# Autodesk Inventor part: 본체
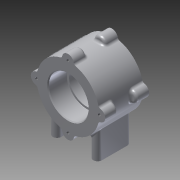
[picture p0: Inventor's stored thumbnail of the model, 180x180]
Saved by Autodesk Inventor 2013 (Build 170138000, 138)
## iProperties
Created: 2015-03
Part Number: 본체
Material: 알루미늄 6061
Document SubType Name: Modeling
Designer: Administrator
Density: 2.71 g/cm^3
Mass: 450.778 g
Surface Area: 332.744 cm^2
Volume: 166.339 cm^3
Author: Administrator
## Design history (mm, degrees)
sketch "스케치1"
  geometry: C1 r 37 at (0, 0); 1 further point
  constraints: 1 centre point, 1 coincident
  dimensions: "d0" = 74 diameter of C1
extrude "돌출1" new body sketch "스케치1" stored distance "d1" = 52; taper "d2" = 0 deg
node "작업 평면1"
sketch "스케치2"
  geometry: L1 (-29, 15)-(-29, -15); L2 (-19, 15)-(-19, -15); L3 (19, 15)-(19, -15); L4 (29, 15)-(29, -15); A1 r 5 centre (-24, 15) between (-19, 15) and (-29, 15); A2 r 5 centre (24, 15) between (29, 15) and (19, 15); A3 r 5 centre (24, -15) between (19, -15) and (29, -15); A4 r 5 centre (-24, -15) between (-29, -15) and (-19, -15); 1 further point
  constraints: 8 end point, 8 point on circle, 7 tangent, 4 centre point, 1 parallel
  dimensions: "d7" = 10 diameter of A1; "d8" = 10 diameter of A2; "d9" = 10 diameter of A3; "d10" = 10 diameter of A4; "d11" = 48 distance of A3.centre A4.centre; "d12" = 15 vertical distance of A2.centre point (0, 0); "d13" = 24 horizontal distance of A2.centre point (0, 0); "d14" = 24 horizontal distance of A1.centre point (0, 0); "d15" = 15 vertical distance of A1.centre point (0, 0); "d16" = 15 vertical distance of A4.centre point (0, 0); "d17" = 24 horizontal distance of point (0, 0) A4.centre; "d18" = 24 horizontal distance of A3.centre point (0, 0)
extrude "돌출2" join sketch "스케치2" stored distance "d19" = 52; taper "d20" = 0 deg
sketch "스케치3"
  geometry: C1 r 7 at (0, 37); C2 r 7 at (37, 0); C3 r 7 at (0, -37); C4 r 7 at (-37, 0)
  constraints: 4 centre point
  dimensions: "d21" = 7 radius of C1; "d22" = 7 radius of C2; "d23" = 7 radius of C3; "d24" = 7 radius of C4
extrude "돌출3" join sketch "스케치3" distance "d25" = 15; taper "d26" = 0 deg
sketch "스케치4"
  geometry: A1 r 37 centre (0, 0) between (6.969, 36.338) and (-6.969, 36.338) reference; A2 r 7 centre (0, 37) between (6.969, 36.338) and (-6.969, 36.338) reference; A3 r 37 centre (0, 0) between (36.338, -6.969) and (36.338, 6.969) reference; A4 r 7 centre (37, 0) between (36.338, -6.969) and (36.338, 6.969) reference; A5 r 37 centre (0, 0) between (-36.338, 6.969) and (-36.338, -6.969) reference; A6 r 7 centre (-37, 0) between (-36.338, 6.969) and (-36.338, -6.969) reference; A7 r 37 centre (0, 0) between (-6.969, -36.338) and (6.969, -36.338) reference; A8 r 7 centre (0, -37) between (-6.969, -36.338) and (6.969, -36.338) reference
extrude "돌출4" join sketch "스케치4" distance "d27" = 15; taper "d28" = 0 deg
sketch "스케치5"
  geometry: C1 r 23.5 at (0, 0)
  constraints: 1 centre point
  dimensions: "d30" = 47 diameter of C1
extrude "돌출5" cut sketch "스케치5" distance "d31" = 22; taper "d32" = 0 deg
sketch "스케치6"
  geometry: C1 r 21 at (0, 0); 1 further point
  constraints: 1 centre point, 1 coincident
  dimensions: "d33" = 42 diameter of C1
extrude "돌출6" cut sketch "스케치6" distance "d35" = 8; taper "d36" = 0 deg
sketch "스케치7"
  geometry: C1 r 23.5 at (0, 0) reference
extrude "돌출7" cut sketch "스케치7" distance "d37" = 22; taper "d38" = 0 deg
sketch "스케치8"
  geometry: L1 (-29, 15)-(-29, -15) reference; L2 (-19, -15)-(-19, 15) reference; A1 r 5 centre (24, 15) between (29, 15) and (19, 15) reference; A2 r 5 centre (24, -15) between (19, -15) and (29, -15) reference; A3 r 5 centre (-24, 15) between (-19, 15) and (-29, 15) reference; A4 r 5 centre (-24, -15) between (-29, -15) and (-19, -15) reference; 5 further points
  constraints: 4 coincident
hole "구멍1" sketch "스케치8" at (-24, 15), (24, 15), (24, -15), (-24, -15) diameter "d39" = 4.134; stored, may be unused: countersink angle "d43" = 90 deg, drill point angle "d45" = 118 deg; dims "d40" = 6, "d41" = 4, "d42" = 2, "d44" = 8
sketch "스케치9"
  geometry: A1 r 7 centre (37, 0) between (36.338, -6.969) and (36.338, 6.969) reference; A2 r 7 centre (0, 37) between (6.969, 36.338) and (-6.969, 36.338) reference; A3 r 7 centre (-37, 0) between (-36.338, 6.969) and (-36.338, -6.969) reference; A4 r 7 centre (0, -37) between (-6.969, -36.338) and (6.969, -36.338) reference; 4 further points
  constraints: 4 coincident
hole "구멍2" sketch "스케치9" at (0, 37), (37, 0), (0, -37), (-37, 0) diameter "d46" = 3.242; stored, may be unused: countersink angle "d50" = 90 deg, drill point angle "d52" = 118 deg; dims "d47" = 8, "d48" = 4, "d49" = 2, "d51" = 11
sketch "스케치10"
  geometry: A1 r 7 centre (0, -37) between (-6.969, -36.338) and (6.969, -36.338) reference; A2 r 7 centre (37, 0) between (36.338, -6.969) and (36.338, 6.969) reference; A3 r 7 centre (0, 37) between (6.969, 36.338) and (-6.969, 36.338) reference; A4 r 7 centre (-37, 0) between (-36.338, 6.969) and (-36.338, -6.969) reference; 4 further points
  constraints: 4 coincident
hole "구멍3" sketch "스케치10" at (0, 37), (-37, 0), (0, -37), (37, 0) diameter "d53" = 3.242; stored, may be unused: countersink angle "d57" = 90 deg, drill point angle "d59" = 118 deg; dims "d54" = 8, "d55" = 4, "d56" = 2, "d58" = 11
node "작업 평면3"
  node "작업 평면2"
sketch "스케치11"
  geometry: 2 further points
  constraints: 1 coincident, 1 other
feature "엠보싱1" sketch "스케치11" dims "d22" = 7, "d62" = 0.5, "d63" = 0
chamfer "모따기1" distance "d64" = 1; stored, may be unused: second distance "d65" = 2, angle "d66" = 45 deg
chamfer "모따기2" distance "d67" = 1; stored, may be unused: second distance "d68" = 2, angle "d69" = 45 deg
fillet "모깎기1" dims "d70" = 0.3
fillet "모깎기2" dims "d71" = 3
node "솔리드1"
node "투영된 루프1"
node "투영된 루프2"
node "투영된 루프3"
node "투영된 루프4"
node "투영된 루프5"
other parameters: "d3" = -56, "d60" = 45 deg, "d61" = 37
